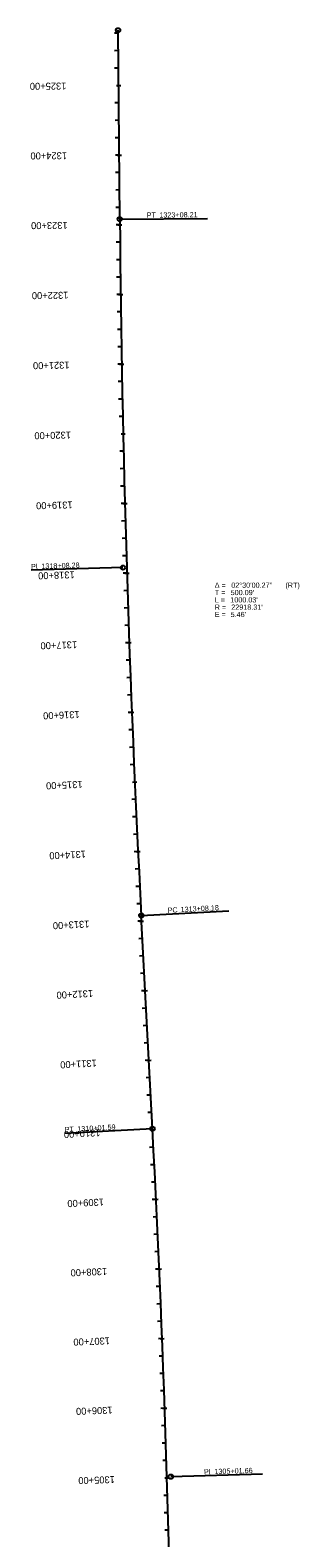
# Model space of a CAD drawing. Extents: x 19548215 to 19548727, y 7547983 to 7562114.
# Drawn here: x 19548238 to 19548624, y 7552414 to 7554578 of the extents above; entities that cross this region are included whole.
import ezdxf

# ---------------------------------------------------------------- set-up
doc = ezdxf.new("R2010")
doc.units = 0
for name, color, linetype in [('Contours Major', 7, 'Continuous'), ('Contours Minor', 7, 'Continuous'), ('Default', 7, 'Continuous'), ('TextAlignment', 7, 'Continuous'), ('TextAlignmentSml', 7, 'Continuous')]:
    doc.layers.add(name, color=color, linetype=linetype)

msp = doc.modelspace()

# ---------------------------------------------------------------- linework, layer by layer
at = {"layer": 'Contours Major'}
for p, q in [((19548362.5, 7554499), (19548368.6, 7554499)), ((19548366.4, 7554399), (19548361, 7554398.9)), ((19548367.3, 7554299), (19548361.9, 7554298.9)), ((19548368.5, 7554199), (19548363, 7554198.9)), ((19548370.1, 7554099), (19548364.6, 7554098.9)), ((19548369, 7553999), (19548375.1, 7553999.1)), ((19548374.6, 7553899.1), (19548369.1, 7553898.9)), ((19548377.5, 7553799.1), (19548372, 7553798.9)), ((19548380.8, 7553699.2), (19548375.3, 7553699)), ((19548384.6, 7553599.2), (19548379.1, 7553599)), ((19548385.7, 7553499.2), (19548391.8, 7553499.5)), ((19548393.4, 7553399.4), (19548388, 7553399.2)), ((19548398.5, 7553299.6), (19548393, 7553299.3)), ((19548403.8, 7553199.7), (19548398.3, 7553199.4)), ((19548409, 7553099.8), (19548403.6, 7553099.6)), ((19548411.2, 7552999.8), (19548417.3, 7553000.1)), ((19548419.3, 7552900.1), (19548413.9, 7552899.8)), ((19548423.9, 7552800.2), (19548418.5, 7552800)), ((19548428.1, 7552700.3), (19548422.6, 7552700.1)), ((19548431.8, 7552600.4), (19548426.4, 7552600.2)), ((19548432, 7552500.3), (19548438.2, 7552500.5))]:
    msp.add_line(p, q, dxfattribs=at)
at = {"layer": 'Contours Minor'}
for p, q in [((19548367.2, 7554307.2), (19548364.8, 7554578.4)), ((19548414.2, 7553001.6), (19548398.1, 7553307.7))]:
    msp.add_line(p, q, dxfattribs=at)
for centre, start, end in [((19571284.6, 7554513.7), 180.51634, 183.01642), ((19525527.6, 7551795.6), 0.51637, 3.01642)]:
    msp.add_arc(centre, 22918.3, start, end, dxfattribs=at)
at = {"layer": 'Default'}
for p, q in [((19548367.2, 7554307.2), (19548364.8, 7554578.4)), ((19548414.2, 7553001.6), (19548398.1, 7553307.7))]:
    msp.add_line(p, q, dxfattribs=at)
for centre, start, end in [((19571284.6, 7554513.7), 180.51634, 183.01642), ((19525527.6, 7551795.6), 0.51637, 3.01642)]:
    msp.add_arc(centre, 22918.3, start, end, dxfattribs=at)
at = {"layer": 'TextAlignment'}
for p, q in [((19548367.2, 7554307.2), (19548493.2, 7554308.3)), ((19548493.2, 7554308.3), (19548493.2, 7554308.3)), ((19548371.7, 7553807.1), (19548239.8, 7553803.1)), ((19548239.8, 7553803.1), (19548239.8, 7553803.1)), ((19548398.1, 7553307.7), (19548523.9, 7553314.4)), ((19548523.9, 7553314.4), (19548523.9, 7553314.4)), ((19548414.2, 7553001.6), (19548288.4, 7552994.9)), ((19548288.4, 7552994.9), (19548288.4, 7552994.9)), ((19548440.5, 7552502.2), (19548572.4, 7552506.2)), ((19548572.4, 7552506.2), (19548572.4, 7552506.2))]:
    msp.add_line(p, q, dxfattribs=at)
for centre in [(19548364.8, 7554578.4), (19548367.2, 7554307.2), (19548371.7, 7553807.1), (19548398.1, 7553307.7), (19548414.2, 7553001.6), (19548440.5, 7552502.2)]:
    msp.add_circle(centre, 3.12, dxfattribs=at)
at = {"layer": 'TextAlignmentSml'}
for p, q in [((19548364.8, 7554574), (19548359.4, 7554573.9)), ((19548365.1, 7554549), (19548359.6, 7554548.9)), ((19548365.3, 7554524), (19548359.8, 7554523.9)), ((19548362.5, 7554499), (19548368.6, 7554499)), ((19548365.7, 7554474), (19548360.3, 7554473.9)), ((19548366, 7554449), (19548360.5, 7554448.9)), ((19548366.2, 7554424), (19548360.7, 7554423.9)), ((19548363.4, 7554399), (19548369.5, 7554399)), ((19548366.6, 7554374), (19548361.2, 7554373.9)), ((19548366.9, 7554349), (19548361.4, 7554348.9)), ((19548367.1, 7554324), (19548361.6, 7554323.9)), ((19548364.3, 7554299), (19548370.4, 7554299)), ((19548367.6, 7554274), (19548362.1, 7554273.9)), ((19548367.8, 7554249), (19548362.4, 7554248.9)), ((19548368.1, 7554224), (19548362.7, 7554223.9)), ((19548365.4, 7554199), (19548371.5, 7554199)), ((19548368.8, 7554174), (19548363.4, 7554173.9)), ((19548369.2, 7554149), (19548363.8, 7554148.9)), ((19548369.6, 7554124), (19548364.2, 7554123.9)), ((19548367, 7554099), (19548373.1, 7554099.1)), ((19548370.5, 7554074), (19548365.1, 7554073.9)), ((19548371, 7554049), (19548365.6, 7554048.9)), ((19548371.5, 7554024), (19548366.1, 7554023.9)), ((19548369, 7553999), (19548375.1, 7553999.1)), ((19548372.7, 7553974), (19548367.2, 7553973.9)), ((19548373.3, 7553949.1), (19548367.8, 7553948.9)), ((19548373.9, 7553924.1), (19548368.4, 7553923.9)), ((19548371.5, 7553899), (19548377.6, 7553899.1)), ((19548375.2, 7553874.1), (19548369.8, 7553873.9)), ((19548375.9, 7553849.1), (19548370.5, 7553848.9)), ((19548376.7, 7553824.1), (19548371.2, 7553823.9)), ((19548374.4, 7553799), (19548380.5, 7553799.2)), ((19548378.2, 7553774.1), (19548372.8, 7553773.9)), ((19548379.1, 7553749.1), (19548373.6, 7553749)), ((19548379.9, 7553724.2), (19548374.5, 7553724)), ((19548377.7, 7553699.1), (19548383.8, 7553699.3)), ((19548381.7, 7553674.2), (19548376.2, 7553674)), ((19548382.6, 7553649.2), (19548377.2, 7553649)), ((19548383.6, 7553624.2), (19548378.1, 7553624)), ((19548381.5, 7553599.1), (19548387.6, 7553599.4)), ((19548385.6, 7553574.3), (19548380.1, 7553574)), ((19548386.6, 7553549.3), (19548381.2, 7553549)), ((19548387.7, 7553524.3), (19548382.2, 7553524.1)), ((19548385.7, 7553499.2), (19548391.8, 7553499.5)), ((19548389.9, 7553474.4), (19548384.4, 7553474.1)), ((19548391, 7553449.4), (19548385.6, 7553449.1)), ((19548392.2, 7553424.4), (19548386.8, 7553424.1)), ((19548390.4, 7553399.3), (19548396.5, 7553399.6)), ((19548394.6, 7553374.5), (19548389.2, 7553374.2)), ((19548395.9, 7553349.5), (19548390.4, 7553349.2)), ((19548397.2, 7553324.5), (19548391.7, 7553324.2)), ((19548395.4, 7553299.4), (19548401.5, 7553299.7)), ((19548399.8, 7553274.6), (19548394.4, 7553274.3)), ((19548401.1, 7553249.6), (19548395.7, 7553249.3)), ((19548402.4, 7553224.7), (19548397, 7553224.4)), ((19548400.7, 7553199.5), (19548406.8, 7553199.9)), ((19548405.1, 7553174.7), (19548399.6, 7553174.4)), ((19548406.4, 7553149.8), (19548400.9, 7553149.5)), ((19548407.7, 7553124.8), (19548402.2, 7553124.5)), ((19548406, 7553099.7), (19548412.1, 7553100)), ((19548410.3, 7553074.9), (19548404.9, 7553074.6)), ((19548411.6, 7553049.9), (19548406.2, 7553049.6)), ((19548413, 7553024.9), (19548407.5, 7553024.7)), ((19548411.2, 7552999.8), (19548417.3, 7553000.1)), ((19548415.6, 7552975), (19548410.1, 7552974.7)), ((19548416.9, 7552950), (19548411.4, 7552949.8)), ((19548418.1, 7552925.1), (19548412.6, 7552924.8)), ((19548416.3, 7552900), (19548422.4, 7552900.3)), ((19548420.5, 7552875.1), (19548415.1, 7552874.9)), ((19548421.7, 7552850.2), (19548416.2, 7552849.9)), ((19548422.8, 7552825.2), (19548417.4, 7552824.9)), ((19548420.9, 7552800.1), (19548427, 7552800.3)), ((19548425, 7552775.2), (19548419.5, 7552775)), ((19548426.1, 7552750.3), (19548420.6, 7552750)), ((19548427.1, 7552725.3), (19548421.6, 7552725.1)), ((19548425, 7552700.2), (19548431.1, 7552700.4)), ((19548429.1, 7552675.3), (19548423.6, 7552675.1)), ((19548430, 7552650.3), (19548424.5, 7552650.1)), ((19548430.9, 7552625.4), (19548425.5, 7552625.2)), ((19548428.8, 7552600.3), (19548434.9, 7552600.5)), ((19548432.7, 7552575.4), (19548427.2, 7552575.2)), ((19548433.5, 7552550.4), (19548428.1, 7552550.2)), ((19548434.3, 7552525.4), (19548428.9, 7552525.2)), ((19548432, 7552500.3), (19548438.2, 7552500.5)), ((19548435.9, 7552475.4), (19548430.4, 7552475.3)), ((19548436.6, 7552450.4), (19548431.1, 7552450.3)), ((19548437.3, 7552425.5), (19548431.8, 7552425.3))]:
    msp.add_line(p, q, dxfattribs=at)

# ---------------------------------------------------------------- texts
at = {"layer": 'Contours Major'}
for s, rotation, p in [('1325+00', 180.5163, (19548290.5, 7554503.3)), ('1320+00', 181.2869, (19548297, 7554002.4)), ('1315+00', 182.5369, (19548313.6, 7553501)), ('1310+00', 183.0124, (19548339.1, 7553001)), ('1305+00', 181.7624, (19548360, 7552503.1))]:
    msp.add_text(s, height=10.02, rotation=rotation, dxfattribs=at).set_placement(p)
at = {"layer": 'TextAlignment'}
for s, rotation, p in [('PT', 0.5163, (19548406, 7554309.2)), ('1323+08.21', 0.5163, (19548424.1, 7554309.4)), ('PI ', 1.7664, (19548239.8, 7553804.7)), ('1318+08.28', 1.7664, (19548254.7, 7553805.2)), ('PC', 3.0164, (19548436.1, 7553311.4)), ('1313+08.18', 3.0164, (19548454.7, 7553312.4)), ('PT', 3.0164, (19548288.3, 7552996.6)), ('1310+01.59', 3.0164, (19548306.4, 7552997.5)), ('PI ', 1.7664, (19548488.2, 7552505.3)), ('1305+01.66', 1.7664, (19548503.2, 7552505.8))]:
    msp.add_text(s, height=7.5, rotation=rotation, dxfattribs=at).set_placement(p)
for s, p in [('T = ', (19548503.6, 7553767.5)), ('Δ = ', (19548503.6, 7553778)), ("500.09'", (19548526.4, 7553767.5)), ('02°30\'00.27"', (19548527.3, 7553778)), (' (RT)', (19548602.2, 7553778)), ('L = ', (19548503.6, 7553757)), ('R = ', (19548503.6, 7553746.5)), ("1000.03'", (19548525.9, 7553757)), ("22918.31'", (19548527.3, 7553746.5)), ('E = ', (19548503.6, 7553736)), ("5.46'", (19548526.4, 7553736))]:
    msp.add_text(s, height=7.5, dxfattribs=at).set_placement(p)
at = {"layer": 'TextAlignmentSml'}
for s, rotation, p in [('1325+00', 180.5163, (19548290.5, 7554503.3)), ('1324+00', 180.5163, (19548291.4, 7554403.3)), ('1323+00', 180.5369, (19548292.3, 7554303.3)), ('1322+00', 180.7869, (19548293.4, 7554203)), ('1321+00', 181.0369, (19548295, 7554102.7)), ('1320+00', 181.2869, (19548297, 7554002.4)), ('1319+00', 181.5369, (19548299.4, 7553902.1)), ('1318+00', 181.7869, (19548302.3, 7553801.8)), ('1317+00', 182.0369, (19548305.7, 7553701.5)), ('1316+00', 182.2869, (19548309.4, 7553601.3)), ('1315+00', 182.5369, (19548313.6, 7553501)), ('1314+00', 182.7869, (19548318.3, 7553400.8)), ('1313+00', 183.0164, (19548323.3, 7553300.6)), ('1312+00', 183.0164, (19548328.6, 7553200.8)), ('1311+00', 183.0164, (19548333.9, 7553100.9)), ('1310+00', 183.0124, (19548339.1, 7553001)), ('1309+00', 182.7624, (19548344.2, 7552901.5)), ('1308+00', 182.5124, (19548348.8, 7552801.9)), ('1307+00', 182.2624, (19548352.9, 7552702.3)), ('1306+00', 182.0124, (19548356.7, 7552602.7)), ('1305+00', 181.7624, (19548360, 7552503.1))]:
    msp.add_text(s, height=10.02, rotation=rotation, dxfattribs=at).set_placement(p)

doc.saveas('drawing.dxf')
